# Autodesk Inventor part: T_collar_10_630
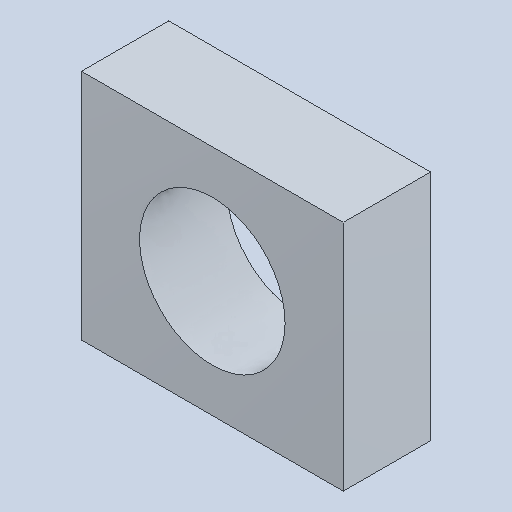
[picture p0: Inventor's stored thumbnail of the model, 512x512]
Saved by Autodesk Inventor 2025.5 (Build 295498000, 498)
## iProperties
Created: 2026-10
Part Number: T_collar_10_630
Material: Genérico
Document SubType Name: Modeling
Designer: Luis M
Density: 1 g/cm^3
Appearance: Valor por defecto
Author: Luis M
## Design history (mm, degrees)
feature "Base1"
node "Sólido1"
